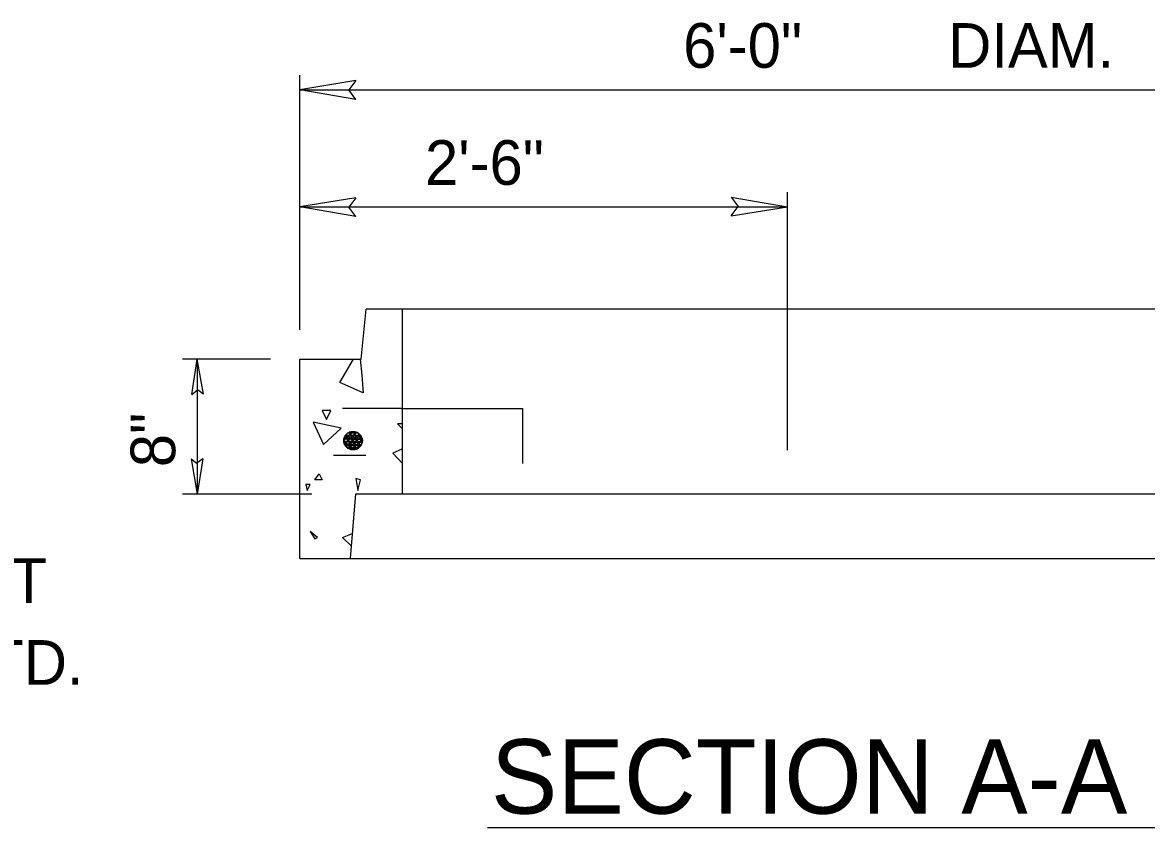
# Model space of a CAD drawing. Extents: x 26.41 to 33.74, y 20.66 to 30.6.
# Drawn here: x 29.019 to 30.528, y 27.311 to 28.392 of the extents above; entities that cross this region are included whole.
import ezdxf

# ---------------------------------------------------------------- set-up
doc = ezdxf.new("R2010")
doc.units = 0
for name, color, linetype in [('DETL-DIMS', 7, 'Continuous'), ('DETL-LINE', 7, 'Continuous'), ('DETL-NOTE', 7, 'Continuous'), ('DETL-PATT', 7, 'Continuous'), ('DETL-TITL', 7, 'Continuous')]:
    doc.layers.add(name, color=color, linetype=linetype)

msp = doc.modelspace()

# ---------------------------------------------------------------- linework, layer by layer
at = {"layer": 'DETL-DIMS'}
for p, q in [((29.3909, 27.9792), (29.3909, 28.3214)), ((29.4664, 28.314), (29.3909, 28.3017)), ((29.4664, 28.314), (29.4569, 28.3014)), ((29.4663, 28.2888), (29.3909, 28.3017)), ((29.3909, 28.3017), (30.9456, 28.3017)), ((29.4663, 28.2888), (29.4569, 28.3014)), ((30.0458, 27.8178), (30.0458, 28.1641)), ((29.4664, 28.1567), (29.3909, 28.1445)), ((29.4663, 28.1315), (29.3909, 28.1445)), ((29.3909, 28.1445), (30.0458, 28.1445)), ((29.4664, 28.1567), (29.4569, 28.1442)), ((29.4663, 28.1315), (29.4569, 28.1442)), ((29.9703, 28.1574), (30.0458, 28.1445)), ((29.9703, 28.1574), (29.9797, 28.1448)), ((29.9703, 28.1323), (29.9797, 28.1448)), ((29.9703, 28.1323), (30.0458, 28.1445)), ((29.3516, 27.9399), (29.2336, 27.9399)), ((29.2459, 27.8926), (29.2533, 27.9399)), ((29.2616, 27.8928), (29.2533, 27.9399)), ((29.2533, 27.9399), (29.2533, 27.7588)), ((29.2459, 27.8926), (29.2537, 27.8986)), ((29.2616, 27.8928), (29.2537, 27.8986)), ((29.245, 27.8059), (29.2533, 27.7588)), ((29.245, 27.8059), (29.2529, 27.8001)), ((29.2607, 27.8061), (29.2529, 27.8001)), ((29.2607, 27.8061), (29.2533, 27.7588)), ((29.4073, 27.7588), (29.2336, 27.7588))]:
    msp.add_line(p, q, dxfattribs=at)
at = {"layer": 'DETL-LINE'}
for p, q in [((29.4734, 27.9399), (29.4803, 28.0069)), ((30.6113, 28.0069), (29.4803, 28.0069)), ((29.5288, 27.7588), (29.5288, 28.0069)), ((29.3909, 27.6721), (29.3909, 27.9399)), ((29.3909, 27.9399), (29.4734, 27.9399)), ((29.5269, 27.8736), (29.4482, 27.8736)), ((29.4616, 27.8423), (29.4521, 27.8332)), ((29.4621, 27.8421), (29.4525, 27.8329)), ((29.4516, 27.8292), (29.4608, 27.8197)), ((29.4517, 27.8351), (29.4609, 27.8255)), ((29.4615, 27.8365), (29.452, 27.8273)), ((29.462, 27.8362), (29.4525, 27.827)), ((29.4663, 27.8322), (29.453, 27.8324)), ((29.4662, 27.8292), (29.453, 27.8294)), ((29.4662, 27.828), (29.453, 27.8283)), ((29.4664, 27.8363), (29.4531, 27.8365)), ((29.4663, 27.8333), (29.4531, 27.8336)), ((29.4664, 27.8375), (29.4532, 27.8377)), ((29.4546, 27.8321), (29.4638, 27.8225)), ((29.4547, 27.8379), (29.4639, 27.8284)), ((29.4644, 27.8336), (29.4549, 27.8244)), ((29.4645, 27.8394), (29.455, 27.8302)), ((29.4648, 27.8333), (29.4553, 27.8241)), ((29.465, 27.8391), (29.4554, 27.8299)), ((29.4704, 27.8291), (29.4571, 27.8294)), ((29.4703, 27.828), (29.4571, 27.8282)), ((29.4705, 27.8362), (29.4572, 27.8364)), ((29.4705, 27.8333), (29.4572, 27.8335)), ((29.4704, 27.8321), (29.4572, 27.8323)), ((29.4705, 27.8374), (29.4573, 27.8376)), ((29.4574, 27.8291), (29.4666, 27.8196)), ((29.4576, 27.8349), (29.4668, 27.8254)), ((29.4577, 27.8408), (29.4668, 27.8313)), ((29.4673, 27.8306), (29.4577, 27.8214)), ((29.4673, 27.8364), (29.4578, 27.8272)), ((29.4678, 27.8361), (29.4582, 27.8269)), ((29.4677, 27.8303), (29.4582, 27.8211)), ((29.4604, 27.832), (29.4696, 27.8224)), ((29.4605, 27.8378), (29.4697, 27.8283)), ((29.4701, 27.8276), (29.4606, 27.8184)), ((29.4702, 27.8335), (29.4607, 27.8243)), ((29.4703, 27.8393), (29.4608, 27.8301)), ((29.4705, 27.8273), (29.461, 27.8181)), ((29.4707, 27.8331), (29.4611, 27.8239)), ((29.4708, 27.839), (29.4612, 27.8298)), ((29.4745, 27.8279), (29.4612, 27.8281)), ((29.4746, 27.8332), (29.4613, 27.8334)), ((29.4745, 27.832), (29.4613, 27.8322)), ((29.4745, 27.8291), (29.4613, 27.8293)), ((29.4634, 27.8349), (29.4726, 27.8253)), ((29.4635, 27.8406), (29.4727, 27.8311)), ((29.4731, 27.8305), (29.4635, 27.8213)), ((29.4732, 27.8363), (29.4637, 27.8271)), ((29.4735, 27.8302), (29.464, 27.821)), ((29.4736, 27.836), (29.4641, 27.8268)), ((29.4662, 27.8251), (29.4529, 27.8253)), ((29.4661, 27.8239), (29.4529, 27.8241)), ((29.4703, 27.8238), (29.457, 27.8241)), ((29.4702, 27.8209), (29.457, 27.8211)), ((29.4703, 27.825), (29.4571, 27.8252)), ((29.4363, 27.8108), (29.4797, 27.8108)), ((29.459, 27.6721), (29.4662, 27.7589)), ((30.8691, 27.7588), (29.4662, 27.7588)), ((29.3909, 27.6721), (30.9456, 27.6721))]:
    msp.add_line(p, q, dxfattribs=at)
for points in [[(29.5269, 27.8736), (29.6898, 27.8736), (29.6898, 27.7998)], [(29.4622, 27.8429), (29.4551, 27.836)], [(29.4629, 27.8429), (29.4555, 27.8357)], [(29.4672, 27.842), (29.458, 27.8331)], [(29.4622, 27.8429), (29.4581, 27.8389)], [(29.4677, 27.8418), (29.4583, 27.8328)], [(29.4629, 27.8429), (29.4585, 27.8386)], [(29.4672, 27.842), (29.4609, 27.8359)], [(29.4677, 27.8418), (29.4613, 27.8356)], [(29.4614, 27.8429), (29.467, 27.8371)], [(29.4614, 27.8429), (29.4698, 27.8341)], [(29.4591, 27.8392), (29.45, 27.8305)], [(29.4561, 27.8363), (29.45, 27.8305)], [(29.4532, 27.8335), (29.45, 27.8305)], [(29.45, 27.8309), (29.455, 27.8256)], [(29.45, 27.8309), (29.4579, 27.8226)], [(29.4502, 27.8306), (29.45, 27.8305)], [(29.4587, 27.8395), (29.4501, 27.8312)], [(29.4557, 27.8366), (29.4501, 27.8312)], [(29.4527, 27.8338), (29.4501, 27.8312)], [(29.4621, 27.8293), (29.4501, 27.8295)], [(29.458, 27.8294), (29.4501, 27.8295)], [(29.4539, 27.8294), (29.4501, 27.8295)], [(29.4622, 27.8322), (29.4502, 27.8324)], [(29.458, 27.8323), (29.4502, 27.8324)], [(29.4539, 27.8324), (29.4502, 27.8324)], [(29.4621, 27.8281), (29.4502, 27.8283)], [(29.458, 27.8282), (29.4502, 27.8283)], [(29.4538, 27.8283), (29.4502, 27.8283)], [(29.4622, 27.8334), (29.4504, 27.8336)], [(29.4581, 27.8335), (29.4504, 27.8336)], [(29.4539, 27.8335), (29.4504, 27.8336)], [(29.4585, 27.8337), (29.4508, 27.8262)], [(29.4556, 27.8308), (29.4508, 27.8262)], [(29.4526, 27.828), (29.4508, 27.8262)], [(29.459, 27.8333), (29.451, 27.8257)], [(29.456, 27.8305), (29.451, 27.8257)], [(29.453, 27.8276), (29.451, 27.8257)], [(29.4512, 27.8357), (29.458, 27.8285)], [(29.4622, 27.8364), (29.4516, 27.8366)], [(29.4581, 27.8364), (29.4516, 27.8366)], [(29.454, 27.8365), (29.4516, 27.8366)], [(29.4623, 27.8375), (29.4523, 27.8377)], [(29.4582, 27.8376), (29.4523, 27.8377)], [(29.454, 27.8377), (29.4523, 27.8377)], [(29.4614, 27.8307), (29.4529, 27.8225)], [(29.4584, 27.8278), (29.4529, 27.8225)], [(29.4618, 27.8304), (29.4532, 27.8221)], [(29.4589, 27.8276), (29.4532, 27.8221)], [(29.4535, 27.8391), (29.461, 27.8314)], [(29.4664, 27.8404), (29.4552, 27.8406)], [(29.4623, 27.8405), (29.4552, 27.8406)], [(29.4582, 27.8406), (29.4552, 27.8406)], [(29.4643, 27.8277), (29.4561, 27.8198)], [(29.4647, 27.8274), (29.4565, 27.8195)], [(29.4569, 27.8416), (29.464, 27.8342)], [(29.4664, 27.8416), (29.4571, 27.8417)], [(29.4624, 27.8416), (29.4571, 27.8417)], [(29.4582, 27.8417), (29.4571, 27.8417)], [(29.4701, 27.8403), (29.4573, 27.8406)], [(29.4683, 27.8416), (29.4574, 27.8417)], [(29.4729, 27.8373), (29.4614, 27.8375)], [(29.4736, 27.8361), (29.4614, 27.8364)], [(29.4683, 27.8416), (29.4615, 27.8417)], [(29.4701, 27.8403), (29.4615, 27.8405)], [(29.4633, 27.829), (29.4708, 27.8212)], [(29.4708, 27.8397), (29.4638, 27.8329)], [(29.4712, 27.8394), (29.4642, 27.8327)], [(29.4747, 27.8279), (29.4653, 27.828)], [(29.4749, 27.832), (29.4654, 27.8322)], [(29.4749, 27.8291), (29.4654, 27.8292)], [(29.4729, 27.8373), (29.4655, 27.8375)], [(29.4736, 27.8361), (29.4655, 27.8363)], [(29.4747, 27.8332), (29.4655, 27.8333)], [(29.4683, 27.8416), (29.4656, 27.8416)], [(29.4701, 27.8403), (29.4656, 27.8404)], [(29.4662, 27.8319), (29.4734, 27.8245)], [(29.4664, 27.8377), (29.4748, 27.8289)], [(29.4748, 27.8321), (29.4665, 27.8242)], [(29.4734, 27.8365), (29.4666, 27.83)], [(29.4749, 27.8315), (29.467, 27.8239)], [(29.4736, 27.836), (29.4671, 27.8297)], [(29.4686, 27.8414), (29.4699, 27.8399)], [(29.4686, 27.8414), (29.4728, 27.837)], [(29.4686, 27.8414), (29.4736, 27.8361)], [(29.4691, 27.8289), (29.4734, 27.8245)], [(29.4692, 27.8348), (29.4748, 27.8289)], [(29.4694, 27.8406), (29.4736, 27.8361)], [(29.4748, 27.8321), (29.4695, 27.827)], [(29.4749, 27.8315), (29.4699, 27.8267)], [(29.4721, 27.8318), (29.4748, 27.8289)], [(29.4722, 27.8376), (29.4736, 27.8361)], [(29.462, 27.8252), (29.4511, 27.8254)], [(29.4579, 27.8252), (29.4511, 27.8254)], [(29.4538, 27.8253), (29.4511, 27.8254)], [(29.462, 27.824), (29.4517, 27.8242)], [(29.4579, 27.8241), (29.4517, 27.8242)], [(29.4538, 27.8241), (29.4517, 27.8242)], [(29.4555, 27.825), (29.4529, 27.8225)], [(29.4559, 27.8247), (29.4532, 27.8221)], [(29.4661, 27.821), (29.4542, 27.8212)], [(29.462, 27.821), (29.4542, 27.8212)], [(29.4578, 27.8211), (29.4542, 27.8212)], [(29.4545, 27.8263), (29.4624, 27.818)], [(29.4661, 27.8198), (29.4558, 27.82)], [(29.4619, 27.8199), (29.4558, 27.82)], [(29.4578, 27.8199), (29.4558, 27.82)], [(29.4613, 27.8248), (29.4561, 27.8198)], [(29.4583, 27.822), (29.4561, 27.8198)], [(29.4617, 27.8246), (29.4565, 27.8195)], [(29.4588, 27.8217), (29.4565, 27.8195)], [(29.4688, 27.8197), (29.4569, 27.8199)], [(29.4574, 27.8233), (29.4624, 27.818)], [(29.4602, 27.8203), (29.4624, 27.818)], [(29.4603, 27.8261), (29.4672, 27.819)], [(29.4672, 27.8247), (29.4603, 27.8182)], [(29.4642, 27.8219), (29.4603, 27.8182)], [(29.4612, 27.819), (29.4603, 27.8182)], [(29.4676, 27.8245), (29.461, 27.8181)], [(29.4646, 27.8216), (29.461, 27.8181)], [(29.4617, 27.8187), (29.461, 27.8181)], [(29.473, 27.8238), (29.4611, 27.824)], [(29.4704, 27.8209), (29.4611, 27.821)], [(29.4688, 27.8197), (29.4611, 27.8199)], [(29.4736, 27.8249), (29.4612, 27.8252)], [(29.4632, 27.8232), (29.4672, 27.819)], [(29.4704, 27.8209), (29.4652, 27.821)], [(29.4688, 27.8197), (29.4652, 27.8198)], [(29.4736, 27.8249), (29.4653, 27.8251)], [(29.473, 27.8238), (29.4653, 27.8239)], [(29.4661, 27.826), (29.4708, 27.8212)], [(29.4661, 27.8202), (29.4672, 27.819)], [(29.474, 27.8256), (29.4669, 27.8188)], [(29.473, 27.8246), (29.4669, 27.8188)], [(29.47, 27.8218), (29.4669, 27.8188)], [(29.467, 27.8189), (29.4669, 27.8188)], [(29.4733, 27.8242), (29.4683, 27.8195)], [(29.4733, 27.8242), (29.4683, 27.8195)], [(29.4704, 27.8215), (29.4683, 27.8195)], [(29.469, 27.823), (29.4708, 27.8212)], [(29.474, 27.8256), (29.4694, 27.8212)], [(29.4733, 27.8242), (29.4698, 27.8209)], [(29.472, 27.8259), (29.4734, 27.8245)], [(29.474, 27.8256), (29.4724, 27.8241)], [(29.4733, 27.8242), (29.4728, 27.8237)]]:
    msp.add_lwpolyline(points, dxfattribs=at)
msp.add_circle((29.4625, 27.8305), 0.0125, dxfattribs=at)
at = {"layer": 'DETL-PATT'}
for points in [[(29.472, 27.9399), (29.4744, 27.9184), (29.4763, 27.8948), (29.4447, 27.9085), (29.4633, 27.9399)], [(29.5288, 27.8533), (29.5221, 27.8533), (29.5282, 27.8472), (29.5288, 27.8482)], [(29.5288, 27.819), (29.5282, 27.8193), (29.5159, 27.8137), (29.5288, 27.7998)], [(29.4604, 27.6886), (29.4485, 27.7005), (29.4618, 27.706)]]:
    msp.add_lwpolyline(points, dxfattribs=at)
for points in [[(29.4211, 27.8708), (29.4268, 27.859), (29.4329, 27.8708)], [(29.4089, 27.8552), (29.423, 27.8255), (29.4466, 27.8472)], [(29.4169, 27.7859), (29.4211, 27.7778), (29.4112, 27.7778)], [(29.399, 27.7717), (29.4008, 27.7637), (29.4051, 27.7717)], [(29.4664, 27.7797), (29.4688, 27.7637), (29.4725, 27.7778)], [(29.4112, 27.6986), (29.415, 27.7005), (29.4051, 27.7085)]]:
    msp.add_lwpolyline(points, close=True, dxfattribs=at)
at = {"layer": 'DETL-TITL'}
msp.add_line((29.6428, 27.311), (30.6936, 27.311), dxfattribs=at)

# ---------------------------------------------------------------- texts
at = {"layer": 'DETL-NOTE'}
for s, p in [('6\'-0"', (29.9057, 28.3312)), ('DIAM.', (30.2615, 28.3312)), ('2\'-6"', (29.5591, 28.174)), ('ADJUSTMENT', (28.5125, 27.6127)), ('RING SEE STD.', (28.5125, 27.5027))]:
    msp.add_text(s, height=0.05998, dxfattribs=at).set_placement(p)
msp.add_text('8"', height=0.05998, rotation=90, dxfattribs=at).set_placement((29.2238, 27.7949))
at = {"layer": 'DETL-TITL'}
msp.add_text('SECTION A-A', height=0.099994, dxfattribs=at).set_placement((29.6476, 27.3296))

doc.saveas('drawing.dxf')
